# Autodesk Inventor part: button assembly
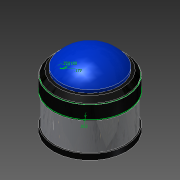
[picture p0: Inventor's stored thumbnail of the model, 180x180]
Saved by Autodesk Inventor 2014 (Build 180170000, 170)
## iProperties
Created: 2013-07
Part Number: button assembly
Material: Generic
Document SubType Name: Modeling
Designer: Trip
Density: 1 g/cm^3
Appearance: Default
Author: Trip
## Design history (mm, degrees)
derived "sparkfun big button.ipt"
  sketch "Sketch3"
    geometry: C1 r 49.125 at (0, 0) reference; C2 r 39.725 at (0, 0) reference; C3 r 43.85 at (0, 0) reference
  sketch "Sketch6"
    geometry: C1 r 43.85 at (0, 0) reference; C2 r 14.375 at (0, 0) reference; C3 r 12 at (0, 0) reference
sketch "Sketch4"
  geometry: C1 r 49.125 at (0, 0) reference; C2 r 49.125 at (0, 0) reference; C3 r 49.919 at (0, 0); A1 r 3 centre (0, 43.85) between (2.998, 43.747) and (-2.998, 43.747) reference; A2 r 43.85 centre (0, 0) between (-2.998, 43.747) and (2.998, 43.747) reference; A3 r 3 centre (0, 43.85) between (2.998, 43.747) and (-2.998, 43.747) reference; A4 r 43.85 centre (0, 0) between (-2.998, 43.747) and (2.998, 43.747) reference; A5 r 3.794 centre (0, 43.85) between (3.74, 44.487) and (-3.74, 44.487); A6 r 44.644 centre (0, 0) between (-3.74, 44.487) and (3.74, 44.487)
  constraints: 4 point on circle, 3 centre point, 1 other
  dimensions: "d1" = 0.79375 radial gap between concentric circles of C3 C1; "d2" = 0.79375 radial gap between concentric circles of A6 A2
extrude "Extrusion1" new body sketch "Sketch4" distance "d3" = 5.08; taper "d4" = 0 deg
sketch "Sketch5"
  geometry: C1 r 49.919 at (0, 0) reference; C2 r 43.85 at (0, 0) reference; A1 r 44.644 centre (0, 0) between (-3.74, 44.487) and (3.74, 44.487) reference; A2 r 44.644 centre (0, 0) between (3.74, 44.487) and (-3.74, 44.487)
  constraints: 2 point on circle, 1 centre point, 1 coincident
workplane "Work Plane1"
extrude "Extrusion2" join sketch "Sketch5" stored distance "d6" = 5.08; taper "d7" = 0 deg
sketch "Sketch7"
  geometry: C1 r 49.919 at (0, 0) reference; C2 r 13.588 at (0, 0); A1 r 12 centre (0, 0) between (6.5, -10.087) and (6.5, 10.087) reference
  constraints: 1 centre point, 1 coincident
  dimensions: "d8" = 1.5875 radial gap between concentric circles of C2 A1
extrude "Extrusion3" join sketch "Sketch7" distance "d9" = 6.35; taper "d10" = 0 deg
workplane "Work Plane2"
sketch "Sketch8"
  geometry: C1 r 49.919 at (0, 0) reference; C2 r 46.744 at (0, 0); C3 r 43.569 at (0, 0)
  constraints: 2 centre point
  dimensions: "d11" = 3.175 radial gap between concentric circles of C1 C2; "d12" = 3.175 radial gap between concentric circles of C2 C3
extrude "Extrusion4" join sketch "Sketch8" stored distance "d13" = 50.8; taper "d14" = 0 deg
feature "Move Face3" dims "d20" = 9.525
sketch "Sketch9"
  geometry: C1 r 46.744 at (0, 0); C2 r 48.331 at (0, 0); C3 r 49.919 at (0, 0) reference
  constraints: 2 centre point
  dimensions: "d17" = 1.5875 radial gap between concentric circles of C2 C1
extrude "Extrusion5" cut sketch "Sketch9" distance "d18" = 1.5875; taper "d19" = 0 deg
extrude "Extrusion15" join sketch "Sketch9" distance "d44" = 1.5875; taper "d45" = 0 deg
sketch "Sketch10"
  geometry: L1 (-34.169, 2.381)-(-34.169, -2.381); L2 (-34.169, -2.381)-(-38.294, -4.762); L3 (-38.294, -4.762)-(-42.418, -2.381); L4 (-42.418, -2.381)-(-42.418, 2.381); L5 (-42.418, 2.381)-(-38.294, 4.762); L6 (-38.294, 4.762)-(-34.169, 2.381); L7 (0, 44.644)-(0, -44.644); L8 (34.169, 2.381)-(34.169, -2.381); L9 (34.169, -2.381)-(38.294, -4.762); L10 (38.294, -4.762)-(42.418, -2.381); L11 (42.418, -2.381)-(42.418, 2.381); L12 (42.418, 2.381)-(38.294, 4.762); L13 (38.294, 4.762)-(34.169, 2.381); L14 (-44.644, 0)-(44.644, 0); C1 r 13.588 at (0, 0) reference; C2 r 44.644 at (0, 0) reference; C3 r 2.248 at (-38.294, 0); C4 r 2.248 at (38.294, 0); A1 r 44.644 centre (0, 0) between (0, 44.644) and (0, -44.644) reference; A2 r 44.644 centre (0, 0) between (3.74, -44.487) and (-3.74, -44.487) reference; A3 r 44.644 centre (0, 0) between (-3.74, -44.487) and (3.74, -44.487) reference; 3 further points
  constraints: 28 end point, 8 symmetric about line, 4 point on circle, 2 centre point, 2 coincident, 1 midpoint, 1 parallel, 1 perpendicular, 1 point on line, 1 vertical, 14 other
  dimensions: "d21" = 4.7625 distance of L5.end point (-38.294, 0); "d22" = 6.35 distance of point (-38.294, 0) L14.start; "d25" = 4.4958 diameter of C3
  node "Projected Loop2"
extrude "nut relief" cut sketch "Sketch10" distance "d23" = 3.175; taper "d24" = 0 deg
extrude "Extrusion7" cut sketch "Sketch10" stored distance "d26" = 3.175; taper "d27" = 0 deg
sketch "Sketch11"
  geometry: C1 r 49.919 at (0, 0) reference
sketch "Sketch12"
  geometry: L1 (-38.294, 0)-(-43.569, 0); L2 (-38.294, 6.35)-(-43.569, 6.35); L3 (-43.569, -6.35)-(-38.294, -6.35); L4 (-43.104, 6.35)-(-43.104, -6.35); C1 r 2.248 at (-38.294, 0) reference; A1 r 43.569 centre (0, 0) between (-43.569, 0) and (-43.104, 6.35) reference; A2 r 6.35 centre (-38.294, 0) between (-38.294, -6.35) and (-38.294, 6.35); A3 r 6.35 centre (-43.569, 0) between (-43.569, 6.35) and (-46.397, 5.686); A4 r 46.744 centre (0, 0) between (-46.397, 5.686) and (-46.397, -5.686) reference; A5 r 6.35 centre (-43.569, 0) between (-46.397, -5.686) and (-43.569, -6.35); 1 further point
  constraints: 11 point on circle, 10 end point, 5 tangent, 3 centre point, 2 point on line, 1 midpoint, 1 parallel
  dimensions: "d30" = 6.35 radius of A2
extrude "Extrusion10" join sketch "Sketch12" stored distance "d33" = 3.175; taper "d34" = 0 deg
mirror "Mirror1"
sketch "Sketch13"
  geometry: C1 r 2.248 at (38.294, 0) reference; C2 r 2.248 at (-38.294, 0) reference; C3 r 49.919 at (0, 0) reference; C4 r 48.331 at (0, 0) reference; C5 r 46.744 at (0, 0) reference
extrude "Extrusion17" new body sketch "Sketch13" distance "d48" = 6.35; taper "d49" = 0 deg
extrude "Extrusion18" join sketch "Sketch13" distance "d50" = 1.5875; taper "d51" = 0 deg
sketch "Sketch15"
  geometry: L1 (-1.27, 47.321)-(1.27, 47.321); L2 (1.27, 47.321)-(1.27, 42.587); L3 (1.27, 42.587)-(-1.27, 42.587); L4 (-1.27, 42.587)-(-1.27, 47.321); L5 (-1.27, 47.321)-(1.27, 42.587); L6 (1.27, 47.321)-(-1.27, 42.587); 1 further point
  constraints: 12 end point, 2 midpoint, 2 parallel, 1 horizontal, 1 perpendicular
  dimensions: "d52" = 2.54 distance of L2.end L3.end
extrude "Extrusion19" cut sketch "Sketch15" stored distance "d53" = 1.5875; taper "d54" = 0 deg
extrude_surface "ExtrusionSrf1" dims "d55" = 1.5875, "d56" = 0
sketch "Sketch16"
  geometry: L1 (0, 49.919)-(0, -49.919); C1 r 2.248 at (-38.294, 0) reference; C2 r 2.248 at (38.294, 0) reference; C3 r 5.08 at (-38.294, 0); C4 r 2.248 at (38.294, 0); C5 r 5.08 at (38.294, 0); A1 r 49.919 centre (0, 0) between (0, 49.919) and (0, -49.919) reference
  constraints: 3 centre point, 2 coincident, 2 end point, 2 point on circle, 2 symmetric about line, 2 other
  dimensions: "d57" = 10.16 diameter of C3
extrude "Extrusion20" cut sketch "Sketch16" distance "d58" = 3.175; taper "d59" = 0 deg
sketch "Sketch17"
  geometry: L1 (0, 34.881)-(0, 21.752); L2 (-2.54, 34.881)-(-2.54, 21.752); L3 (2.54, 21.752)-(2.54, 34.881); L4 (0, -44.644)-(0, 44.644) reference; C1 r 5.08 at (0, 21.752); A1 r 2.54 centre (0, 34.881) between (2.54, 34.881) and (-2.54, 34.881); A2 r 2.54 centre (0, 21.752) between (-2.54, 21.752) and (2.54, 21.752); 1 further point
  constraints: 8 end point, 4 point on circle, 4 tangent, 3 centre point, 1 coincident, 1 collinear, 1 midpoint, 1 parallel, 1 vertical
  dimensions: "d60" = 5.08 distance between parallel lines of L3 L2; "d61" = 10.16 diameter of C1
extrude "Extrusion22" cut sketch "Sketch17" stored distance "d64" = 3.175; taper "d65" = 0 deg
feature "Solid2::sparkfun big button.ipt" dims "d0" = 10
feature "Solid3::sparkfun big button.ipt" dims "d0" = 10
tag "TaggingFeature1"
node "Projected Loop1"
node "main chamber"
node "backplate"
body "Srf1"
node "black frame"
node "blue button"
other parameters: "d5" = 0.79375, "d15" = 3.175
